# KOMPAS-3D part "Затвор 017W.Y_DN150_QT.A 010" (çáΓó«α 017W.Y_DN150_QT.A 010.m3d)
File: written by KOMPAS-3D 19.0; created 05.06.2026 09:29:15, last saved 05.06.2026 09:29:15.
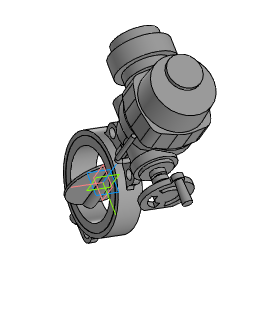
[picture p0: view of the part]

Document properties: Автор: Энергия; Полное имя файла: ..\..\..\3d для проектировщиков\x.x Тип 017W.Y(S) Затвор дисковый поворотный межфланцевый\Затвор 017W.Y(S)_DN32-DN1200_QT.A_MT903.A\Затвор 017W.Y_DN150_QT.A 010.a3d

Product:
- Part/product: Затвор 017W.Y_DN150_QT.A 010
    Масса: 45.8554

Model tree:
1. Операция без истории:1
